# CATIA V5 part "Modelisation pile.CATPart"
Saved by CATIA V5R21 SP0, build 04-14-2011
Part number: Modelisation pile
Bounding box of the stored display mesh (mm): x 0 to 78.3, y 0 to 62, z 0 to 30
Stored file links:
  C:\Users\2027.DESARCY-LEMIE30\Desktop\V16(05.04.2023)\Modelisation pile.CATPart
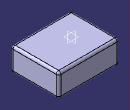
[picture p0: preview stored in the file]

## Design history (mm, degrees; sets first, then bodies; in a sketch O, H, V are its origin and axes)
Body1 (main body)
  Sketch1 on xy-plane, origin (0, 0, 0), H (1, 0, 0), V (0, 1, 0)
    line L1 (0, 62) -> (78.3, 62)
    line L2 (78.3, 62) -> (78.3, 0)
    line L3 (78.3, 0) -> (0, 0)
    line L4 (0, 0) -> (0, 62)
    point P3 (78.3, 0)
    point P4 (0, 0)
    length L2 = 62
    length L3 = 78.3
    horizontal: L1 H, L3 H
    vertical: L2 V, L4 V
    coincidence: P3 H, P4 O
  Pad1: profile Sketch1, direction (0, 0, 1), length 30
  Fillet1: radius 3, on edge [face of Pad1 from Sketch1.L4 | end face of Pad1]; edge [face of Pad1 from Sketch1.L1 | end face of Pad1]; edge [face of Pad1 from Sketch1.L3 | end face of Pad1]; edge [face of Pad1 from Sketch1.L2 | end face of Pad1]
  Fillet2: radius 3, on edge [start face of Pad1 | face of Pad1 from Sketch1.L1]; edge [start face of Pad1 | face of Pad1 from Sketch1.L4]; edge [start face of Pad1 | face of Pad1 from Sketch1.L3]; edge [start face of Pad1 | face of Pad1 from Sketch1.L2]
  Fillet3: radius 3, on edge [face of Pad1 from Sketch1.L3 | face of Pad1 from Sketch1.L4]; edge [face of Pad1 from Sketch1.L1 | face of Pad1 from Sketch1.L2]; edge [face of Pad1 from Sketch1.L2 | face of Pad1 from Sketch1.L3]; edge [face of Pad1 from Sketch1.L4 | face of Pad1 from Sketch1.L1]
